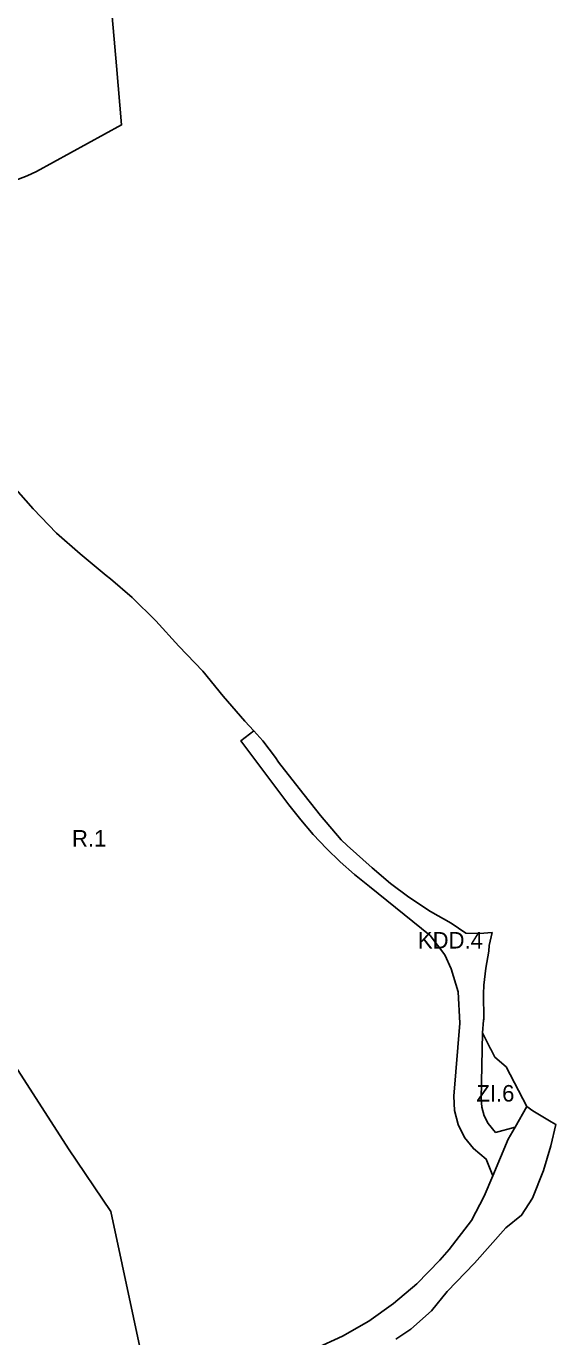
# Model space of a CAD drawing. Extents: x 7422965 to 7424741, y 5551047 to 5553849.
# Drawn here: x 7424058 to 7424444, y 5551939 to 5552892 of the extents above; entities that cross this region are included whole.
import ezdxf

# ---------------------------------------------------------------- set-up
doc = ezdxf.new("R2010")
doc.units = 0
doc.layers.add('linie_rozgraniczajace', color=7, linetype='Continuous')
doc.layers.add('oznaczenia_przeznaczen', color=7, linetype='Continuous')

msp = doc.modelspace()

# ---------------------------------------------------------------- linework, layer by layer
at = {"layer": 'linie_rozgraniczajace'}
for points in [[(7424119.81, 5552913.52), (7424124.09, 5552863.72), (7424127.86, 5552820.64), (7424065.95, 5552786.72), (7424059.13, 5552783.75), (7424017.18, 5552767.52), (7424000.77, 5552762.43), (7423992.54, 5552761.23), (7423986.42, 5552782.73), (7423980.88, 5552808.54), (7423966.03, 5552847.79), (7423941.64, 5552864.17), (7423902.73, 5552895.58)], [(7424049.23, 5552557.69), (7424063.4, 5552541.4), (7424080.56, 5552523.74), (7424097.59, 5552508.86), (7424116.6, 5552493.11), (7424119.71, 5552490.65), (7424135.61, 5552476.94), (7424152.75, 5552460.03), (7424169.49, 5552441.6), (7424186.93, 5552423.53), (7424201.79, 5552405.25), (7424217.51, 5552387.04), (7424224.03, 5552379.91), (7424214.52, 5552372.75), (7424249.54, 5552326.2), (7424258.18, 5552315.24), (7424267.3, 5552304.68), (7424276.89, 5552294.55), (7424286.93, 5552284.86), (7424297.39, 5552275.63), (7424308.26, 5552266.88), (7424352.3, 5552231.13), (7424362.98, 5552217.19), (7424367.68, 5552206.95), (7424372.73, 5552190.24), (7424374.06, 5552167.42), (7424369.72, 5552114.3), (7424370.11, 5552103.85), (7424372.69, 5552093.72), (7424377.33, 5552084.35), (7424383.84, 5552076.17), (7424393.09, 5552068.59), (7424397.9, 5552056.32), (7424391.71, 5552041.65), (7424382.38, 5552023.84), (7424366.19, 5552002.74), (7424359.34, 5551995.07), (7424342.65, 5551977.88), (7424325.83, 5551963.55), (7424307.79, 5551950.82), (7424288.66, 5551939.77), (7424268.6, 5551930.5)], [(7424039.42, 5552153.32), (7424089.19, 5552076.05), (7424120.1, 5552030.52), (7424144.75, 5551914.84)], [(7424144.75, 5551914.84), (7424120.1, 5552030.52), (7424089.19, 5552076.05), (7424039.42, 5552153.32)], [(7424268.6, 5551930.5), (7424288.66, 5551939.77), (7424307.79, 5551950.82), (7424325.83, 5551963.55), (7424342.65, 5551977.88), (7424359.34, 5551995.07), (7424366.19, 5552002.74), (7424382.38, 5552023.84), (7424391.71, 5552041.65), (7424397.9, 5552056.32), (7424409.21, 5552083.12), (7424414.16, 5552091.81), (7424422.75, 5552106.88), (7424427.06, 5552103.61), (7424440.45, 5552095.75), (7424443.85, 5552093.75), (7424440.11, 5552078.14), (7424434.82, 5552060.38), (7424426.84, 5552040.15), (7424418.99, 5552027.7), (7424407.48, 5552018.6), (7424384.74, 5551992.99), (7424364.72, 5551972.25), (7424353.29, 5551958.26), (7424338.43, 5551944.9), (7424327.49, 5551937.52)]]:
    msp.add_lwpolyline(points, dxfattribs=at)
for points in [[(7424214.52, 5552372.75), (7424224.03, 5552379.91), (7424230.55, 5552372.77), (7424239.78, 5552360.7), (7424242.01, 5552357.29), (7424257.19, 5552338.07), (7424272.64, 5552318.47), (7424287.56, 5552300.73), (7424291.91, 5552296.69), (7424310.17, 5552280.3), (7424323.47, 5552269), (7424337, 5552259), (7424352.65, 5552248.76), (7424367.61, 5552240.22), (7424378.48, 5552232.85), (7424388.34, 5552232.59), (7424397.53, 5552233.33), (7424395.39, 5552223.99), (7424395.06, 5552219.76), (7424392.82, 5552207.5), (7424391.55, 5552194.98), (7424391.22, 5552188.71), (7424391.35, 5552170.44), (7424391.29, 5552169.68), (7424390.55, 5552160.42), (7424389.65, 5552112.52), (7424389.98, 5552106.23), (7424391.64, 5552100.15), (7424394.55, 5552094.57), (7424400.01, 5552088.01), (7424414.16, 5552091.81), (7424409.21, 5552083.12), (7424397.9, 5552056.32), (7424393.09, 5552068.59), (7424383.84, 5552076.17), (7424377.33, 5552084.35), (7424372.69, 5552093.72), (7424370.11, 5552103.85), (7424369.72, 5552114.3), (7424374.06, 5552167.42), (7424372.73, 5552190.24), (7424367.68, 5552206.95), (7424362.98, 5552217.19), (7424352.3, 5552231.13), (7424308.26, 5552266.88), (7424297.39, 5552275.63), (7424286.93, 5552284.86), (7424276.89, 5552294.55), (7424267.3, 5552304.68), (7424258.18, 5552315.24), (7424249.54, 5552326.2)], [(7424389.65, 5552112.52), (7424390.55, 5552160.42), (7424396.41, 5552148.81), (7424396.35, 5552148.77), (7424396.56, 5552148.5), (7424399.43, 5552142.81), (7424407.68, 5552135.79), (7424422.75, 5552106.88), (7424414.16, 5552091.81), (7424400.01, 5552088.01), (7424394.55, 5552094.57), (7424391.64, 5552100.15), (7424389.98, 5552106.23)]]:
    msp.add_lwpolyline(points, close=True, dxfattribs=at)

# ---------------------------------------------------------------- texts
at = {"layer": 'oznaczenia_przeznaczen'}
for s, p in [('R.1', (7424091.74, 5552295.83)), ('KDD.4', (7424343.52, 5552221.73)), ('ZI.6', (7424386.07, 5552110.44))]:
    msp.add_text(s, height=12, dxfattribs=at).set_placement(p)

doc.saveas('drawing.dxf')
